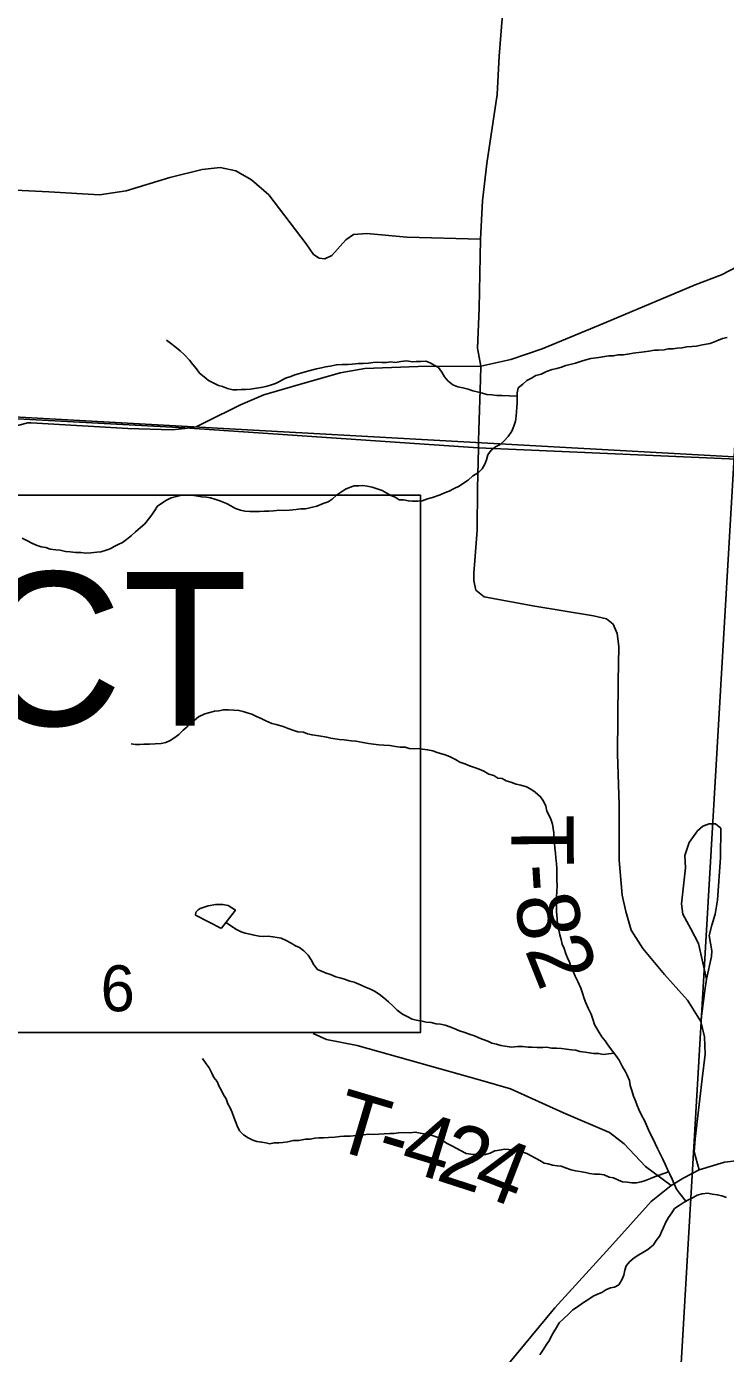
# Model space of a CAD drawing. Extents: x -20.2 to 34, y 0 to 22.
# Drawn here: x 7.395 to 8.033, y 18.094 to 19.304 of the extents above; entities that cross this region are included whole.
import ezdxf

# ---------------------------------------------------------------- set-up
doc = ezdxf.new("R2010")
doc.units = 0
for name, color, linetype in [('Default', 7, 'Continuous'), ('GM_X_County_Road', 7, 'Continuous'), ('GM_X_Minor_River', 7, 'Continuous'), ('GM_X_Section', 7, 'Continuous'), ('GM_X_Section_Text', 7, 'Continuous'), ('GM_X_Township_Road', 7, 'Continuous'), ('GM_X_Township_Road_Text', 7, 'Continuous'), ('SH_Masking', 7, 'Continuous'), ('SH_Text', 7, 'Continuous')]:
    doc.layers.add(name, color=color, linetype=linetype)

msp = doc.modelspace()

# ---------------------------------------------------------------- linework, layer by layer
at = {"layer": 'Default'}
for points in [[(8.1508, 20.9), (2.1, 20.9), (2.1, 19.2514), (2.9253, 19.1951), (4.084, 19.1299), (4.129, 19.1285), (4.5, 19.1063), (4.5753, 19.1032), (5.0716, 19.0751), (5.6168, 19.0426), (5.628, 19.0419), (5.9006, 19.026), (6.5332, 18.9927), (7.3871, 18.9465), (7.5395, 18.9382), (7.8072, 18.9199), (8.043, 18.9097), (8.0485, 19.0914), (8.0709, 19.4522), (8.1316, 20.5548)], [(8.9, 17.8451), (8.9, 18.8721), (8.0404, 18.9117), (7.9819, 17.9077)]]:
    msp.add_lwpolyline(points, close=True, dxfattribs=at)
msp.add_lwpolyline([(8.9, 14.8176), (8.9, 20.9), (8.1508, 20.9), (8.1316, 20.5548), (8.0709, 19.4522), (8.0485, 19.0914), (8.043, 18.9097), (7.8072, 18.9199), (7.5395, 18.9382), (7.3871, 18.9465), (6.5332, 18.9927), (5.9006, 19.026), (5.871, 18.5384), (5.8069, 17.4844), (5.7831, 17.2483), (5.7812, 17.1527), (5.7368, 16.4206)], dxfattribs=at)
at = {"layer": 'GM_X_County_Road'}
msp.add_lwpolyline([(7.8274, 18.0757), (7.8769, 18.1355), (7.9271, 18.1904), (7.9647, 18.2325), (7.983, 18.2472), (7.9946, 18.2541), (8.0087, 18.2613), (8.0317, 18.2685), (8.0558, 18.2712)], dxfattribs=at)
at = {"layer": 'GM_X_Minor_River'}
for points in [[(7.5228, 19.0181), (7.5266, 19.0155), (7.5304, 19.0125), (7.5354, 19.0084), (7.5392, 19.0046), (7.5438, 18.9998), (7.5469, 18.996), (7.5504, 18.9919), (7.5531, 18.9881), (7.5573, 18.9847), (7.5611, 18.9814), (7.5654, 18.9791), (7.5703, 18.9769), (7.5741, 18.9758), (7.5787, 18.974), (7.5833, 18.9729), (7.5871, 18.9729), (7.5909, 18.973), (7.595, 18.973), (7.5996, 18.9735), (7.6049, 18.9743), (7.6091, 18.9751), (7.6136, 18.9759), (7.6178, 18.9771), (7.6223, 18.9787), (7.6261, 18.9803), (7.6313, 18.9834), (7.6363, 18.985), (7.64, 18.9865), (7.6453, 18.9881), (7.6495, 18.9893), (7.654, 18.9905), (7.6597, 18.9921), (7.6643, 18.9929), (7.668, 18.9937), (7.6722, 18.9945), (7.6779, 18.9957), (7.6832, 18.9958), (7.6885, 18.9959), (7.6923, 18.9963), (7.6976, 18.9968), (7.7022, 18.9968), (7.7071, 18.9972), (7.7113, 18.9977), (7.7151, 18.9981), (7.7192, 18.9978), (7.7234, 18.9978), (7.7272, 18.9983), (7.7318, 18.9979), (7.7367, 18.9988), (7.742, 18.9992), (7.7469, 18.9985), (7.7507, 18.9986), (7.7549, 18.9986), (7.7595, 18.999), (7.7633, 18.9976), (7.7671, 18.9953), (7.7709, 18.9931), (7.774, 18.989), (7.7763, 18.9848), (7.7794, 18.9811), (7.784, 18.9773), (7.7886, 18.9755), (7.7932, 18.9748), (7.7981, 18.9733), (7.8023, 18.9718), (7.8061, 18.9711), (7.8111, 18.9697), (7.8149, 18.9686), (7.8194, 18.9683), (7.824, 18.9676), (7.8285, 18.9676), (7.8426, 18.967)], [(7.694, 18.8854), (7.6982, 18.8854), (7.702, 18.8855), (7.7058, 18.8851), (7.7103, 18.8841), (7.7149, 18.8826), (7.7195, 18.8811), (7.7237, 18.8785), (7.7275, 18.8763), (7.7313, 18.8748), (7.7351, 18.8726), (7.7389, 18.8726), (7.7435, 18.8715), (7.7473, 18.8712), (7.7522, 18.8713), (7.756, 18.8717), (7.761, 18.8733), (7.7655, 18.8745), (7.7723, 18.8772), (7.7765, 18.8788), (7.7806, 18.8804), (7.7851, 18.8827), (7.7897, 18.885), (7.7938, 18.8878), (7.798, 18.8905), (7.8021, 18.8943), (7.807, 18.897), (7.8107, 18.9009), (7.813, 18.9051), (7.8148, 18.9089), (7.8159, 18.9135), (7.8189, 18.9177), (7.823, 18.9208), (7.8272, 18.9231), (7.8309, 18.9262), (7.8343, 18.9304), (7.8377, 18.9351), (7.8395, 18.9396), (7.841, 18.9442), (7.8417, 18.9488), (7.842, 18.953), (7.8423, 18.9568), (7.8427, 18.9613), (7.8426, 18.9655), (7.8426, 18.9701), (7.8436, 18.9746), (7.8478, 18.9781), (7.8515, 18.9812), (7.8557, 18.9835), (7.8595, 18.9859), (7.8644, 18.9871), (7.8693, 18.9894), (7.8746, 18.9914), (7.8787, 18.9922), (7.8829, 18.9934), (7.8871, 18.9949), (7.8908, 18.9958), (7.8958, 18.9973), (7.8995, 18.9985), (7.9052, 19.0001), (7.9098, 19.0013), (7.917, 19.0022), (7.9207, 19.003), (7.9261, 19.0038), (7.9306, 19.0039), (7.9344, 19.0047), (7.9393, 19.0047), (7.9435, 19.0055), (7.9484, 19.0064), (7.9583, 19.0076), (7.9628, 19.0081), (7.9677, 19.0089), (7.9715, 19.0089), (7.9765, 19.0094), (7.9803, 19.0102), (7.9848, 19.0102), (7.9886, 19.0107), (7.9928, 19.0111), (7.9973, 19.0119), (8.0019, 19.0123), (8.006, 19.0128), (8.0102, 19.0136), (8.0148, 19.0144), (8.0185, 19.0152), (8.0246, 19.0176), (8.0299, 19.0195), (8.034, 19.0207)], [(7.3913, 18.8375), (7.3955, 18.8353), (7.4008, 18.8327), (7.405, 18.8308), (7.4088, 18.8297), (7.413, 18.829), (7.4168, 18.8275), (7.4221, 18.8269), (7.4259, 18.8265), (7.4309, 18.8254), (7.4351, 18.8251), (7.44, 18.8244), (7.4449, 18.8245), (7.4495, 18.8238), (7.4541, 18.8242), (7.4594, 18.8247), (7.4632, 18.8251), (7.4669, 18.8263), (7.4715, 18.8279), (7.4753, 18.8298), (7.479, 18.8317), (7.4828, 18.8337), (7.4866, 18.8364), (7.4911, 18.8399), (7.4948, 18.8433), (7.4993, 18.8472), (7.5031, 18.8507), (7.5065, 18.8549), (7.5095, 18.8587), (7.5121, 18.8626), (7.5147, 18.8668), (7.5188, 18.8695), (7.523, 18.8722), (7.5271, 18.8742), (7.5309, 18.8753), (7.5358, 18.8765), (7.5404, 18.8766), (7.5453, 18.8767), (7.5499, 18.876), (7.5548, 18.8753), (7.5594, 18.8749), (7.5632, 18.8742), (7.567, 18.8731), (7.5716, 18.8717), (7.5777, 18.8691), (7.5815, 18.8669), (7.5857, 18.8646), (7.5903, 18.8632), (7.5944, 18.8621), (7.599, 18.8618), (7.6036, 18.8618), (7.6077, 18.8619), (7.6123, 18.8623), (7.6161, 18.8623), (7.6206, 18.8624), (7.6259, 18.8632), (7.6309, 18.8629), (7.635, 18.863), (7.6411, 18.8638), (7.6453, 18.8642), (7.6498, 18.8643), (7.6548, 18.8655), (7.6601, 18.8667), (7.6657, 18.8691), (7.6703, 18.8706), (7.674, 18.873), (7.6778, 18.8768), (7.6815, 18.8791), (7.6861, 18.8822), (7.6898, 18.8838), (7.694, 18.8854)], [(7.4907, 18.6499), (7.4948, 18.6492), (7.4986, 18.6492), (7.5024, 18.6496), (7.5074, 18.6497), (7.5127, 18.6498), (7.518, 18.6502), (7.5222, 18.651), (7.5263, 18.653), (7.5305, 18.6557), (7.5342, 18.6584), (7.538, 18.6623), (7.5417, 18.6653), (7.544, 18.6692), (7.5481, 18.6711), (7.5522, 18.6746), (7.5579, 18.6773), (7.5624, 18.6785), (7.5666, 18.6797), (7.5708, 18.6801), (7.5749, 18.681), (7.5795, 18.681), (7.5844, 18.6807), (7.589, 18.6804), (7.5928, 18.6793), (7.5966, 18.6782), (7.6008, 18.6771), (7.605, 18.6749), (7.6092, 18.673), (7.6134, 18.6708), (7.6191, 18.6686), (7.6229, 18.6675), (7.6294, 18.6657), (7.634, 18.6638), (7.6389, 18.662), (7.6428, 18.6609), (7.6477, 18.6606), (7.6515, 18.6591), (7.6557, 18.658), (7.6618, 18.6573), (7.669, 18.6559), (7.6728, 18.6552), (7.6804, 18.6538), (7.685, 18.6535), (7.6914, 18.6528), (7.6956, 18.6525), (7.7021, 18.651), (7.707, 18.6503), (7.7116, 18.6496), (7.7165, 18.6489), (7.7211, 18.6486), (7.7264, 18.6483), (7.7317, 18.6476), (7.7359, 18.6469), (7.7405, 18.6469), (7.7443, 18.6458), (7.7481, 18.6455), (7.7526, 18.6456), (7.7564, 18.6452), (7.761, 18.6445), (7.7656, 18.6434), (7.7698, 18.642), (7.777, 18.6398), (7.7808, 18.6383), (7.7865, 18.6357), (7.7904, 18.6331), (7.7949, 18.6317), (7.7991, 18.6298), (7.8037, 18.6283), (7.8079, 18.6269), (7.8121, 18.625), (7.8167, 18.6224), (7.8213, 18.621), (7.8251, 18.6187), (7.8289, 18.6184), (7.8327, 18.6162), (7.8369, 18.6151), (7.8418, 18.6132), (7.846, 18.6122), (7.851, 18.6107), (7.8552, 18.6085), (7.859, 18.6059), (7.864, 18.6017), (7.8667, 18.5976), (7.8687, 18.5931), (7.8698, 18.5885), (7.873, 18.5821), (7.8749, 18.5768), (7.8753, 18.5726), (7.8762, 18.5688), (7.8762, 18.5643), (7.8766, 18.5593), (7.8771, 18.5548), (7.8775, 18.5506), (7.8779, 18.5457), (7.8784, 18.5407), (7.8788, 18.5358), (7.8789, 18.5301), (7.8789, 18.5252), (7.879, 18.5206), (7.8787, 18.5153)], [(7.8787, 18.5153), (7.8784, 18.5103), (7.8784, 18.5062), (7.8785, 18.502), (7.8785, 18.4971), (7.879, 18.4902), (7.8794, 18.4853), (7.8802, 18.4815), (7.8814, 18.4758), (7.8826, 18.4716), (7.8838, 18.4671), (7.8854, 18.4633), (7.8869, 18.4584), (7.8885, 18.4546), (7.8904, 18.4508), (7.8916, 18.4467), (7.894, 18.4418), (7.8955, 18.438), (7.8979, 18.4331), (7.9006, 18.427), (7.9022, 18.4225), (7.9038, 18.4176), (7.9053, 18.4138), (7.9073, 18.4089), (7.91, 18.4032), (7.9116, 18.3987), (7.9131, 18.3938), (7.9166, 18.3881), (7.9197, 18.3828), (7.9228, 18.3791), (7.9259, 18.3745), (7.9298, 18.3693), (7.9325, 18.3655), (7.9355, 18.3614), (7.9386, 18.3553), (7.941, 18.3515), (7.9429, 18.3478), (7.9449, 18.3429), (7.9457, 18.3383), (7.9473, 18.3338), (7.9488, 18.3285), (7.9504, 18.3243), (7.952, 18.3201), (7.9535, 18.3164), (7.9559, 18.3111), (7.9586, 18.3065), (7.9605, 18.302), (7.9633, 18.2956), (7.966, 18.2907), (7.9683, 18.2854), (7.9707, 18.2809), (7.973, 18.2759), (7.9753, 18.271), (7.9777, 18.2665), (7.9796, 18.2616), (7.9819, 18.2574), (7.9839, 18.2529), (7.9858, 18.2487), (7.9878, 18.2438), (7.9905, 18.2401), (7.9965, 18.2327)], [(7.5731, 18.4818), (7.5858, 18.4983), (7.5793, 18.5024), (7.574, 18.5035), (7.5679, 18.5034), (7.5608, 18.5021), (7.5535, 18.4998), (7.5518, 18.4985), (7.5498, 18.4963), (7.5494, 18.4937), (7.5731, 18.4814)], [(7.5771, 18.487), (7.5868, 18.4805), (7.591, 18.4786), (7.5947, 18.4773), (7.599, 18.4764), (7.6028, 18.4753), (7.6074, 18.4746), (7.6112, 18.4743), (7.6157, 18.4744), (7.6199, 18.474), (7.6237, 18.4733), (7.6275, 18.4726), (7.6321, 18.4704), (7.6367, 18.4682), (7.6405, 18.4656), (7.6443, 18.4641), (7.6481, 18.4611), (7.652, 18.4573), (7.6547, 18.4528), (7.6574, 18.4483), (7.6605, 18.4442), (7.6643, 18.4427), (7.6685, 18.4408), (7.6723, 18.4394), (7.6773, 18.4375), (7.6811, 18.4364), (7.6853, 18.4353), (7.6902, 18.4335), (7.694, 18.4324), (7.7005, 18.4298), (7.7043, 18.428), (7.7089, 18.4261), (7.7127, 18.4243), (7.7169, 18.4217), (7.7212, 18.4183), (7.7254, 18.4146), (7.7296, 18.4108), (7.7331, 18.4071), (7.738, 18.4033), (7.7422, 18.4011), (7.7468, 18.3989), (7.7506, 18.3978), (7.7559, 18.3971), (7.7598, 18.396), (7.7643, 18.3957), (7.7689, 18.3946), (7.7727, 18.3943), (7.7769, 18.3932), (7.7811, 18.3917), (7.7853, 18.3902), (7.7902, 18.388), (7.7948, 18.3866), (7.7997, 18.3847), (7.8036, 18.3836), (7.8078, 18.3818), (7.8116, 18.3803), (7.8158, 18.3788), (7.8196, 18.377), (7.8238, 18.3759), (7.8276, 18.3748), (7.8318, 18.3741), (7.8375, 18.3734), (7.8428, 18.3739), (7.8477, 18.3739), (7.8526, 18.3732), (7.8564, 18.3733), (7.861, 18.373), (7.8659, 18.373), (7.8697, 18.3731), (7.8739, 18.3724), (7.8785, 18.3724), (7.883, 18.3721), (7.8876, 18.3714), (7.8922, 18.3707), (7.896, 18.3704), (7.8998, 18.3693), (7.9047, 18.3686), (7.9085, 18.3682), (7.9123, 18.3675), (7.9169, 18.3676), (7.9211, 18.3665), (7.9309, 18.3677)], [(7.5559, 18.363), (7.559, 18.3581), (7.5617, 18.3544), (7.5644, 18.3495), (7.566, 18.3457), (7.5691, 18.3419), (7.571, 18.3374), (7.573, 18.3336), (7.5749, 18.3298), (7.5772, 18.3261), (7.5788, 18.3215), (7.5811, 18.3178), (7.5827, 18.3136), (7.5843, 18.3094), (7.5858, 18.3053), (7.5874, 18.3015), (7.5894, 18.297), (7.5932, 18.2932), (7.5974, 18.2906), (7.6016, 18.2884), (7.6054, 18.2873), (7.6096, 18.2866), (7.6134, 18.2859), (7.6172, 18.2852), (7.621, 18.286), (7.6252, 18.286), (7.629, 18.2864), (7.6335, 18.2869), (7.6384, 18.2881), (7.6437, 18.2882), (7.6498, 18.2894), (7.654, 18.2894), (7.6581, 18.2902), (7.6619, 18.2907), (7.6661, 18.2907), (7.6707, 18.2908), (7.6763, 18.2912), (7.6809, 18.2917), (7.6847, 18.2921), (7.6904, 18.2922), (7.6957, 18.2926), (7.701, 18.2931), (7.7067, 18.2939), (7.7116, 18.2936), (7.7165, 18.294), (7.7215, 18.2941), (7.7264, 18.2945), (7.7302, 18.2946), (7.7344, 18.295), (7.7401, 18.2954), (7.745, 18.2951), (7.7496, 18.2956), (7.7541, 18.2949), (7.7579, 18.2941), (7.7621, 18.2934), (7.7659, 18.2923), (7.7697, 18.2913), (7.7743, 18.2883), (7.7781, 18.2857), (7.7831, 18.2834), (7.7869, 18.2812), (7.7911, 18.279), (7.7961, 18.2764), (7.8003, 18.2757), (7.8064, 18.2754), (7.8101, 18.2754), (7.8139, 18.2755), (7.8181, 18.2767), (7.8223, 18.2786), (7.8264, 18.2794), (7.831, 18.2802), (7.8351, 18.2799), (7.839, 18.2792), (7.8428, 18.2789), (7.8477, 18.2774), (7.8515, 18.2763), (7.8553, 18.2741), (7.8592, 18.2719), (7.8634, 18.27), (7.8672, 18.2674), (7.871, 18.2667), (7.8748, 18.2656), (7.879, 18.2649), (7.8828, 18.2646), (7.8866, 18.2631), (7.8919, 18.2613), (7.8957, 18.2605), (7.8999, 18.2598), (7.9049, 18.2588), (7.9087, 18.258), (7.9132, 18.2573), (7.9178, 18.2574), (7.922, 18.2567), (7.9265, 18.2548), (7.9304, 18.2541), (7.9349, 18.2519), (7.9387, 18.2504), (7.9429, 18.2501), (7.9471, 18.2494), (7.9513, 18.2495), (7.9558, 18.2503)], [(7.9558, 18.2503), (7.9596, 18.2515), (7.9641, 18.2534), (7.9679, 18.255), (7.9807, 18.2596)], [(7.8632, 18.0926), (7.8662, 18.0972), (7.8695, 18.1021), (7.8721, 18.106), (7.874, 18.1098), (7.8762, 18.1136), (7.8784, 18.1174), (7.881, 18.1217), (7.8848, 18.1255), (7.8897, 18.1301), (7.8934, 18.1336), (7.8976, 18.1363), (7.9021, 18.1398), (7.907, 18.1429), (7.9119, 18.146), (7.916, 18.1479), (7.9198, 18.1495), (7.9236, 18.1518), (7.9277, 18.1538), (7.9315, 18.1542), (7.9353, 18.1565), (7.9379, 18.1611), (7.9398, 18.1653), (7.9408, 18.1699), (7.9419, 18.1737), (7.9453, 18.1776), (7.9494, 18.181), (7.9536, 18.1837), (7.9573, 18.1861), (7.9619, 18.1888), (7.9668, 18.193), (7.9694, 18.1969), (7.9727, 18.2011), (7.9742, 18.2049), (7.9761, 18.2087), (7.9783, 18.2137), (7.9805, 18.2179), (7.9835, 18.2221), (7.9861, 18.226), (7.9902, 18.2287), (7.9948, 18.2318), (7.9989, 18.2341), (8.0031, 18.236), (8.0068, 18.2384), (8.0114, 18.2396), (8.0163, 18.24), (8.0205, 18.2393), (8.0251, 18.2386), (8.0292, 18.2375), (8.0334, 18.236)]]:
    msp.add_lwpolyline(points, dxfattribs=at)
at = {"layer": 'GM_X_Section'}
for points in [[(8.0972, 19.9556), (8.0404, 18.9117), (6.9777, 18.9706), (7.0409, 20.0115)], [(6.9777, 18.9706), (8.0404, 18.9117), (7.9819, 17.9077), (6.915, 17.9639)]]:
    msp.add_lwpolyline(points, close=True, dxfattribs=at)
at = {"layer": 'GM_X_Township_Road'}
for points in [[(7.8075, 18.9263), (7.8078, 18.9361), (7.8092, 18.9823), (7.8094, 18.9944), (7.8064, 19.0109), (7.808, 19.0471), (7.8092, 19.1104), (7.811, 19.1453), (7.8149, 19.1793), (7.8243, 19.2422), (7.8263, 19.2772), (7.8298, 19.3232)], [(7.3489, 19.1568), (7.4156, 19.1535), (7.4618, 19.1506), (7.4861, 19.1544), (7.5261, 19.1664), (7.5555, 19.1737), (7.5718, 19.1756), (7.5862, 19.1726), (7.6005, 19.1645), (7.6163, 19.1506), (7.6502, 19.1059), (7.657, 19.0962), (7.662, 19.0929), (7.6674, 19.0922), (7.6736, 19.0955), (7.6863, 19.1097), (7.6934, 19.1144), (7.7056, 19.1153), (7.7421, 19.1122), (7.8092, 19.1104)], [(7.558, 18.943), (7.5904, 18.959), (7.6117, 18.9684), (7.6378, 18.9759), (7.6813, 18.9883), (7.7039, 18.9924), (7.7524, 18.9942), (7.8094, 18.9944), (7.8369, 19.0004), (7.8653, 19.0103), (7.9218, 19.0337), (8.0048, 19.0685), (8.0289, 19.0776), (8.0434, 19.0854), (8.0487, 19.0909), (8.0502, 19.0925), (8.0542, 19.1014), (8.056, 19.1111), (8.0569, 19.1228), (8.0576, 19.1306)], [(7.2548, 18.7814), (7.2648, 18.7897), (7.2783, 18.7972), (7.2921, 18.8041), (7.3017, 18.8102), (7.3101, 18.8379), (7.3147, 18.8567), (7.3246, 18.8757), (7.3353, 18.894), (7.3527, 18.9157), (7.3694, 18.9315), (7.3802, 18.9384), (7.3966, 18.9427), (7.3996, 18.9426)], [(7.3996, 18.9426), (7.4877, 18.9377), (7.528, 18.9363), (7.5397, 18.9377), (7.5499, 18.9391), (7.558, 18.943)], [(8.0087, 18.2613), (8.0041, 18.2778), (8.005, 18.2897), (8.0114, 18.3444), (8.0139, 18.3668), (8.0133, 18.3826), (8.0101, 18.3968), (7.9979, 18.416), (7.9769, 18.4394), (7.9572, 18.4634), (7.9467, 18.4801), (7.9416, 18.4969), (7.9382, 18.5119), (7.9357, 18.5437), (7.9355, 18.5943), (7.9341, 18.6407), (7.9348, 18.7068), (7.9352, 18.7386), (7.9339, 18.7505), (7.9302, 18.759), (7.924, 18.764), (7.9121, 18.7668), (7.8568, 18.7759), (7.8126, 18.7841), (7.805, 18.7901), (7.803, 18.799), (7.8032, 18.8057), (7.8039, 18.8173), (7.8062, 18.8448), (7.8064, 18.883), (7.8074, 18.9194), (7.8075, 18.9263)], [(8.0101, 18.3968), (8.0137, 18.425), (8.0152, 18.4354), (8.0197, 18.4561), (8.0202, 18.461), (8.0178, 18.4751), (8.02, 18.4845), (8.0231, 18.4947), (8.0254, 18.5074), (8.0279, 18.5464), (8.0284, 18.573), (8.0233, 18.5771), (8.0178, 18.5771), (8.012, 18.5749), (8.0071, 18.5707), (7.9995, 18.5599), (7.9956, 18.548), (7.9961, 18.5367), (7.9924, 18.5039), (7.9938, 18.4945), (8.0009, 18.4811), (8.008, 18.4677), (8.0152, 18.4354)], [(7.6565, 18.3856), (7.6687, 18.3801), (7.6967, 18.3748), (7.8091, 18.3433), (7.8365, 18.3352), (7.885, 18.3133), (7.9268, 18.2953), (7.9403, 18.2851), (7.9597, 18.2643), (7.983, 18.2472)]]:
    msp.add_lwpolyline(points, dxfattribs=at)
at = {"layer": 'SH_Masking'}
msp.add_lwpolyline([(6.0189, 18.3866), (7.7544, 18.3866), (7.7544, 18.8766), (6.0189, 18.8766)], close=True, dxfattribs=at)
at = {"layer": 'SH_Text'}
msp.add_lwpolyline([(6.0189, 18.3866), (6.0189, 18.8766), (7.7544, 18.8766), (7.7544, 18.3866)], close=True, dxfattribs=at)

# ---------------------------------------------------------------- texts
at = {"layer": 'GM_X_Section_Text'}
msp.add_text('6', height=0.0419, rotation=0, dxfattribs=at).set_placement((7.4629, 18.406))
at = {"layer": 'GM_X_Township_Road_Text'}
for s, rotation, p in [('T', 270.42, (7.8372, 18.585)), ('-', 273.559, (7.8376, 18.5391)), ('8', 279.5823, (7.8398, 18.5093)), ('2', 291.7959, (7.8492, 18.4621)), ('T', 343.4465, (7.6711, 18.2814)), ('4', 343.0495, (7.7341, 18.2626)), ('2', 342.067, (7.7673, 18.2525)), ('-', 343.3823, (7.7118, 18.2693)), ('4', 338.8586, (7.7998, 18.242))]:
    msp.add_text(s, height=0.0568, rotation=rotation, dxfattribs=at).set_placement(p)
at = {"layer": 'SH_Text'}
msp.add_text('BEGIN PROJECT', height=0.14, dxfattribs=at).set_placement((6.0889, 18.6666))

doc.saveas('drawing.dxf')
